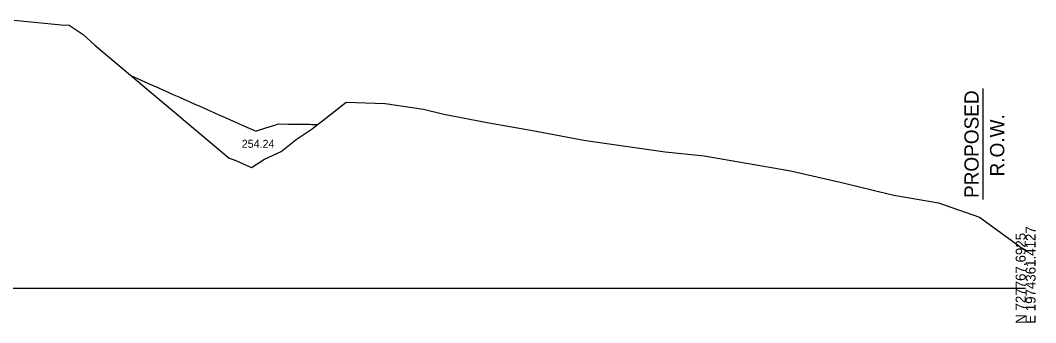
# Model space of a CAD drawing. Extents: x -26 to 1604, y -13 to 9623.
# Drawn here: x 317.3 to 602.8, y 4490.3 to 4575.5 of the extents above; entities that cross this region are included whole.
import ezdxf

# ---------------------------------------------------------------- set-up
doc = ezdxf.new("R2010")
doc.units = 0
for name, color, linetype in [('DTM CONTOURS_MAJOR', 7, 'Continuous'), ('DTM_X_GROUND', 7, 'Continuous'), ('XS_CELL', 7, 'Continuous'), ('XS_P_GROUND', 7, 'Continuous'), ('XS_P_ROW', 7, 'Continuous'), ('XS_P_TX_DCH', 7, 'Continuous')]:
    doc.layers.add(name, color=color, linetype=linetype)

msp = doc.modelspace()

# ---------------------------------------------------------------- linework, layer by layer
at = {"layer": 'DTM_X_GROUND'}
msp.add_lwpolyline([(315.65, 4575.51), (328.79, 4574.26), (331.08, 4574.1), (335.01, 4571.54), (338.31, 4568.48), (376.05, 4536.67), (377.49, 4536.15), (382.36, 4533.99), (386.04, 4536.39), (390.73, 4538.57), (394.91, 4541.91), (399.12, 4544.75), (401.96, 4546.93), (408.99, 4552.42), (419.83, 4552.08), (419.89, 4552.06), (419.93, 4552.07), (430.68, 4550.44), (436.41, 4549.09), (448.64, 4546.69), (461.39, 4544.5), (473.79, 4542.09), (474.8, 4541.94), (475.77, 4541.75), (476.97, 4541.54), (498.65, 4538.46), (509.63, 4537.29), (533.45, 4533.18), (533.47, 4533.18), (533.49, 4533.17), (549.11, 4529.59), (561.35, 4526.64), (562.91, 4526.23), (575.51, 4524.12), (587.02, 4520.04), (599.07, 4511.29), (600, 4510.85)], dxfattribs=at)
at = {"layer": 'XS_CELL'}
msp.add_line((100, 4500), (600, 4500), dxfattribs=at)
at = {"layer": 'XS_P_GROUND'}
for points in [[(348.58, 4559.82), (350.26, 4559.08), (350.49, 4558.98), (353.53, 4557.62), (355.96, 4556.54), (356.8, 4556.17), (358.94, 4555.21), (360.07, 4554.71), (361.91, 4553.9), (363.34, 4553.26), (364.86, 4552.58), (366.61, 4551.8), (367.8, 4551.27), (369.88, 4550.35), (370.73, 4549.97), (373.15, 4548.89), (373.64, 4548.68), (376.42, 4547.44), (376.53, 4547.39), (377.32, 4547.04), (378.88, 4546.35), (379.7, 4545.98), (381.04, 4545.39), (382.97, 4544.53), (383.19, 4544.43), (383.62, 4544.24)], [(400.83, 4546.06), (399.32, 4546.08), (398.63, 4546.1), (396.05, 4546.14), (393.94, 4546.17), (392.78, 4546.19), (389.92, 4546.24), (389.51, 4546.11), (389.06, 4545.97), (386.24, 4545.07), (383.62, 4544.24)]]:
    msp.add_lwpolyline(points, dxfattribs=at)
at = {"layer": 'XS_P_ROW'}
msp.add_line((588, 4556.27), (588, 4525), dxfattribs=at)

# ---------------------------------------------------------------- texts
at = {"layer": 'DTM CONTOURS_MAJOR'}
for p in [(377.28, 4546.98), (389.88, 4546.18), (400.79, 4546), (383.58, 4544.18), (383.58, 4544.18)]:
    msp.add_text('X', height=0.12, dxfattribs=at).set_placement(p)
at = {"layer": 'XS_CELL'}
for s, p in [('E 1974361.4127', (602.8, 4490)), ('N 727767.6925', (600, 4490))]:
    msp.add_text(s, height=2.8, rotation=90, dxfattribs=at).set_placement(p)
at = {"layer": 'XS_P_ROW'}
for s, p in [('PROPOSED', (586.8, 4525.44)), ('R.O.W.', (594, 4531.51))]:
    msp.add_text(s, height=4, rotation=90, dxfattribs=at).set_placement(p)
at = {"layer": 'XS_P_TX_DCH'}
msp.add_text('254.24', height=2.25, dxfattribs=at).set_placement((379.6, 4539.58))

doc.saveas('drawing.dxf')
